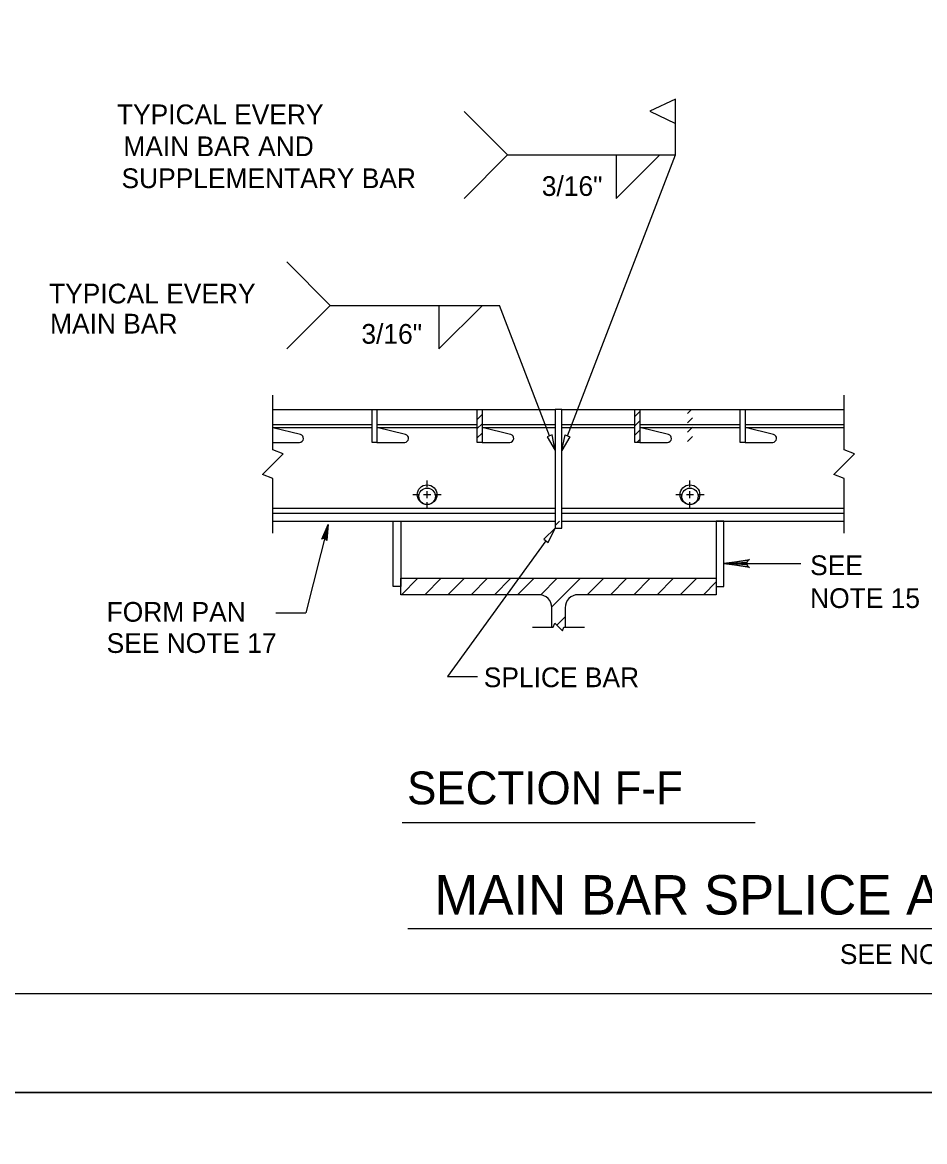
# Model space of a CAD drawing. Extents: x -24512 to -22484, y 4569 to 6351.
# Drawn here: x -24013.4 to -23876.1, y 5155.5 to 5325.8 of the extents above; entities that cross this region are included whole.
import ezdxf

# ---------------------------------------------------------------- set-up
doc = ezdxf.new("R2010")
doc.units = 0
for name, color, linetype in [('10', 7, 'Continuous'), ('2', 7, 'Continuous'), ('3', 7, 'Continuous'), ('4', 7, 'Continuous'), ('5', 7, 'Continuous'), ('9', 7, 'Continuous'), ('PLT-BNDY', 7, 'Continuous')]:
    doc.layers.add(name, color=color, linetype=linetype)

# ---------------------------------------------------------------- blocks, each defined once
blk = doc.blocks.new('JUQ002')
at = {"layer": '4'}
for p, q in [((72.87075, 24.39975), (72.993375, 24.522375)), ((72.87075, 24.114625), (73.021875, 24.265875)), ((72.87075, 23.8295), (73.021875, 23.98075)), ((72.87075, 23.544375), (73.021875, 23.695625))]:
    blk.add_line(p, q, dxfattribs=at)
blk = doc.blocks.new('JUQ001')
at = {"layer": '4'}
for p, q in [((66.419125, 24.506), (66.4355, 24.522375)), ((66.419125, 24.220875), (66.570375, 24.372125)), ((66.419125, 23.93575), (66.570375, 24.087)), ((66.419125, 23.650625), (66.570375, 23.801875)), ((66.567875, 23.514375), (66.570375, 23.51675))]:
    blk.add_line(p, q, dxfattribs=at)
blk = doc.blocks.new('JUQ004')
at = {"layer": '4'}
for p, q in [((69.644875, 24.310375), (69.796125, 24.4615)), ((69.644875, 24.02525), (69.796125, 24.176375)), ((69.644875, 23.740125), (69.796125, 23.89125)), ((69.70425, 23.514375), (69.796125, 23.60625))]:
    blk.add_line(p, q, dxfattribs=at)
blk = doc.blocks.new('SYM036')
at = {"layer": '3'}
for p, q in [((89.35625, 63.69525), (89.860375, 64.19925)), ((90.069125, 63.69525), (90.573125, 64.19925)), ((90.781875, 63.69525), (91.285875, 64.19925)), ((91.49475, 63.69525), (91.99875, 64.19925)), ((92.2075, 63.69525), (92.7115, 64.19925)), ((92.920375, 63.69525), (93.424375, 64.19925)), ((93.628875, 63.691), (94.137125, 64.19925)), ((93.972625, 63.321875), (94.85, 64.19925)), ((95.05875, 63.69525), (95.56275, 64.19925)), ((95.7715, 63.69525), (96.275625, 64.19925)), ((96.484375, 63.69525), (96.988375, 64.19925)), ((97.197125, 63.69525), (97.70125, 64.19925)), ((97.91, 63.69525), (98.414, 64.19925)), ((98.62275, 63.69525), (99.014, 64.0865)), ((94.121125, 62.757625), (94.377, 63.013375))]:
    blk.add_line(p, q, dxfattribs=at)

msp = doc.modelspace()

# ---------------------------------------------------------------- linework, layer by layer
at = {"layer": '10'}
for p, q in [((-23955.64, 5204.12), (-23901.93, 5204.12)), ((-23777.59, 5187.94), (-23954.81, 5187.94))]:
    msp.add_line(p, q, dxfattribs=at)
for points in [[(-23967.75, 5247.3), (-23967.57, 5247.34), (-23966.91, 5249.46), (-23967.75, 5247.3), (-23967.88, 5247.21), (-23966.91, 5249.46), (-23967.34, 5247.28), (-23967.2, 5247.16), (-23966.91, 5249.46), (-23967.13, 5247.02), (-23967.2, 5247.16)], [(-23903.01, 5243.06), (-23903.15, 5243.32), (-23906.7, 5243.52), (-23903.01, 5243.06), (-23902.82, 5242.89), (-23906.7, 5243.52), (-23903.15, 5243.7), (-23903.02, 5243.96), (-23906.7, 5243.52), (-23902.82, 5244.14), (-23903.02, 5243.96)]]:
    msp.add_lwpolyline(points, dxfattribs=at)
at = {"layer": '2'}
msp.add_line((-23353.75, 5178.04), (-24137.79, 5178.04), dxfattribs=at)
at = {"layer": '4'}
for p, q in [((-23975.33, 5266.94), (-23960.23, 5266.94)), ((-23959.48, 5266.94), (-23944.23, 5266.94)), ((-23943.48, 5266.94), (-23932.36, 5266.94)), ((-23931.36, 5266.94), (-23920.23, 5266.94)), ((-23919.48, 5266.94), (-23904.23, 5266.94)), ((-23903.48, 5266.94), (-23888.38, 5266.94)), ((-23975.33, 5264.68), (-23960.23, 5264.68)), ((-23975.33, 5264.18), (-23960.23, 5264.18)), ((-23971.13, 5263.14), (-23975.33, 5264.15)), ((-23959.48, 5264.68), (-23944.23, 5264.68)), ((-23959.48, 5264.18), (-23944.23, 5264.18)), ((-23955.14, 5263.14), (-23959.48, 5264.18)), ((-23943.48, 5264.68), (-23932.36, 5264.68)), ((-23943.48, 5264.18), (-23932.36, 5264.18)), ((-23939.14, 5263.14), (-23943.48, 5264.18)), ((-23931.36, 5264.68), (-23920.23, 5264.68)), ((-23931.36, 5264.18), (-23920.23, 5264.18)), ((-23919.48, 5264.68), (-23904.23, 5264.68)), ((-23919.48, 5264.18), (-23904.23, 5264.18)), ((-23915.14, 5263.14), (-23919.48, 5264.18)), ((-23903.48, 5264.68), (-23888.38, 5264.68)), ((-23903.48, 5264.18), (-23888.38, 5264.18)), ((-23899.14, 5263.14), (-23903.48, 5264.18)), ((-23975.33, 5261.94), (-23971.26, 5261.94)), ((-23959.48, 5261.94), (-23955.26, 5261.94)), ((-23943.48, 5261.94), (-23939.26, 5261.94)), ((-23919.48, 5261.94), (-23915.26, 5261.94)), ((-23903.48, 5261.94), (-23899.27, 5261.94)), ((-23975.33, 5251.94), (-23932.36, 5251.94)), ((-23975.33, 5251.19), (-23932.36, 5251.19)), ((-23931.36, 5251.94), (-23888.38, 5251.94)), ((-23931.36, 5251.19), (-23888.38, 5251.19)), ((-23975.33, 5249.94), (-23932.36, 5249.94)), ((-23931.36, 5249.94), (-23888.38, 5249.94)), ((-23955.85, 5238.76), (-23955.85, 5241.26)), ((-23955.85, 5241.26), (-23907.86, 5241.26)), ((-23907.86, 5241.26), (-23907.86, 5238.76)), ((-23934.86, 5238.76), (-23955.85, 5238.76)), ((-23907.86, 5238.76), (-23928.86, 5238.76)), ((-23932.86, 5233.84), (-23932.86, 5236.76)), ((-23930.86, 5236.76), (-23930.86, 5233.84)), ((-23935.8, 5233.84), (-23932.86, 5233.84)), ((-23930.86, 5233.84), (-23927.91, 5233.84))]:
    msp.add_line(p, q, dxfattribs=at)
for points in [[(-23975.33, 5248.11), (-23975.33, 5256.42), (-23976.88, 5257.07), (-23973.78, 5260.17), (-23975.33, 5260.81), (-23975.33, 5269.13)], [(-23888.38, 5248.11), (-23888.38, 5256.42), (-23889.94, 5257.07), (-23886.83, 5260.17), (-23888.38, 5260.81), (-23888.38, 5269.13)], [(-23932.86, 5233.84), (-23932.68, 5233.84), (-23932.44, 5234.42), (-23931.27, 5233.26), (-23931.03, 5233.84), (-23930.86, 5233.84)]]:
    msp.add_lwpolyline(points, dxfattribs=at)
for points in [[(-23959.48, 5266.94), (-23959.48, 5261.94), (-23960.23, 5261.94), (-23960.23, 5266.94)], [(-23943.48, 5266.94), (-23943.48, 5261.94), (-23944.23, 5261.94), (-23944.23, 5266.94)], [(-23932.36, 5248.89), (-23931.36, 5248.89), (-23931.36, 5266.94), (-23932.36, 5266.94)], [(-23919.48, 5266.94), (-23919.48, 5261.94), (-23920.23, 5261.94), (-23920.23, 5266.94)], [(-23903.48, 5266.94), (-23903.48, 5261.94), (-23904.23, 5261.94), (-23904.23, 5266.94)], [(-23955.85, 5249.94), (-23955.85, 5240.01), (-23957.01, 5240.01), (-23957.01, 5249.94)], [(-23907.86, 5249.94), (-23907.86, 5240.01), (-23906.7, 5240.01), (-23906.7, 5249.94)]]:
    msp.add_lwpolyline(points, close=True, dxfattribs=at)
for centre, radius in [((-23951.85, 5253.98), 1.5), ((-23911.86, 5253.98), 1.5), ((-23951.85, 5253.73), 1.25), ((-23911.86, 5253.73), 1.25)]:
    msp.add_circle(centre, radius, dxfattribs=at)
for centre, radius, start, end in [((-23971.28, 5262.55), 0.61, 271.249, 76.5605), ((-23955.28, 5262.55), 0.61, 271.249, 76.5605), ((-23939.28, 5262.55), 0.61, 271.249, 76.5605), ((-23915.28, 5262.55), 0.61, 271.249, 76.5605), ((-23899.28, 5262.55), 0.61, 271.249, 76.5605), ((-23934.86, 5236.76), 2, 0, 90), ((-23928.86, 5236.76), 2, 90, 180)]:
    msp.add_arc(centre, radius, start, end, dxfattribs=at)
at = {"layer": '5'}
msp.add_line((-23931.69, 5249.94), (-23932.36, 5249.28), dxfattribs=at)
at = {"layer": '9'}
for p, q in [((-23914.04, 5305.68), (-23914.04, 5314.17)), ((-23946.22, 5312.3), (-23939.6, 5305.68)), ((-23946.22, 5299.06), (-23939.6, 5305.68)), ((-23939.6, 5305.68), (-23914.04, 5305.68)), ((-23930.49, 5262.95), (-23914.04, 5305.68)), ((-23923.08, 5305.68), (-23923.08, 5299.06)), ((-23923.08, 5299.06), (-23916.46, 5305.68)), ((-23973.21, 5289.4), (-23966.59, 5282.78)), ((-23973.21, 5276.16), (-23966.59, 5282.78)), ((-23966.59, 5282.78), (-23940.86, 5282.78)), ((-23950.07, 5276.16), (-23943.45, 5282.78)), ((-23950.07, 5282.78), (-23950.07, 5276.16)), ((-23933.22, 5262.95), (-23940.86, 5282.78)), ((-23951.85, 5255.12), (-23951.85, 5256.14)), ((-23911.86, 5255.12), (-23911.86, 5256.14)), ((-23952.99, 5253.98), (-23954.01, 5253.98)), ((-23951.31, 5253.98), (-23952.4, 5253.98)), ((-23951.85, 5253.44), (-23951.85, 5254.53)), ((-23949.7, 5253.98), (-23950.72, 5253.98)), ((-23912.99, 5253.98), (-23914.01, 5253.98)), ((-23911.31, 5253.98), (-23912.4, 5253.98)), ((-23911.86, 5253.44), (-23911.86, 5254.53)), ((-23909.7, 5253.98), (-23910.72, 5253.98)), ((-23951.85, 5251.83), (-23951.85, 5252.85)), ((-23911.86, 5251.83), (-23911.86, 5252.85)), ((-23966.91, 5249.46), (-23970.29, 5236.01)), ((-23933.77, 5246.95), (-23948.77, 5226.32)), ((-23906.7, 5243.52), (-23894.96, 5243.52)), ((-23974.86, 5236.01), (-23970.29, 5236.01)), ((-23948.77, 5226.32), (-23944.18, 5226.32))]:
    msp.add_line(p, q, dxfattribs=at)
for points in [[(-23914.04, 5314.17), (-23917.97, 5312.31), (-23914.04, 5310.45)], [(-23932.84, 5263.09), (-23933.59, 5262.8), (-23932.36, 5260.71)], [(-23930.87, 5263.09), (-23930.12, 5262.8), (-23931.36, 5260.71)], [(-23934.09, 5247.19), (-23933.44, 5246.72), (-23932.36, 5248.89)]]:
    msp.add_lwpolyline(points, close=True, dxfattribs=at)
at = {"layer": 'PLT-BNDY'}
for points in [[(-24179.75, 5757.04), (-23338.75, 5757.04), (-23338.75, 5163.04), (-24179.75, 5163.04)], [(-24179.75, 5163.04), (-23338.75, 5163.04), (-23338.75, 4569.04), (-24179.75, 4569.04)]]:
    msp.add_lwpolyline(points, close=True, dxfattribs=at)

# ---------------------------------------------------------------- block references
at = {"layer": '3', "xscale": 4.959843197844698, "yscale": 4.959843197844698}
msp.add_blockref('SYM036', (-24398.95, 4922.84), dxfattribs=at)
at = {"layer": '4', "xscale": 4.959842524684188, "yscale": 4.959842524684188}
for name, p in [('JUQ001', (-24273.66, 5145.31)), ('JUQ004', (-24265.66, 5145.31)), ('JUQ002', (-24273.66, 5145.31))]:
    msp.add_blockref(name, p, dxfattribs=at)

# ---------------------------------------------------------------- texts
at = {"layer": '10'}
msp.add_text('MAIN BAR SPLICE AT PANEL ENDS', height=6.0008, dxfattribs=at).set_placement((-23950.75, 5190.09))
at = {"layer": '9'}
for s, height, p in [('TYPICAL EVERY', 2.9999, (-23999.05, 5310.35)), ('MAIN BAR AND', 2.9999, (-23998.08, 5305.49)), ('SUPPLEMENTARY BAR', 2.9999, (-23998.36, 5300.63)), ('3/16"', 3, (-23934.4, 5299.44)), ('TYPICAL EVERY', 2.9999, (-24009.39, 5283.08)), ('MAIN BAR', 3, (-24009.23, 5278.5)), ('3/16"', 3, (-23961.85, 5276.95)), ('SEE', 3, (-23893.57, 5241.74)), ('NOTE 15', 3, (-23893.57, 5236.74)), ('FORM PAN', 3, (-24000.62, 5234.65)), ('SEE NOTE 17', 2.9999, (-24000.62, 5229.9)), ('SPLICE BAR', 3, (-23943.23, 5224.69)), ('SECTION F-F', 5, (-23954.9, 5206.86)), ('SEE NOTES 17 & 18', 2.9999, (-23889.05, 5182.57))]:
    msp.add_text(s, height=height, dxfattribs=at).set_placement(p)

doc.saveas('drawing.dxf')
